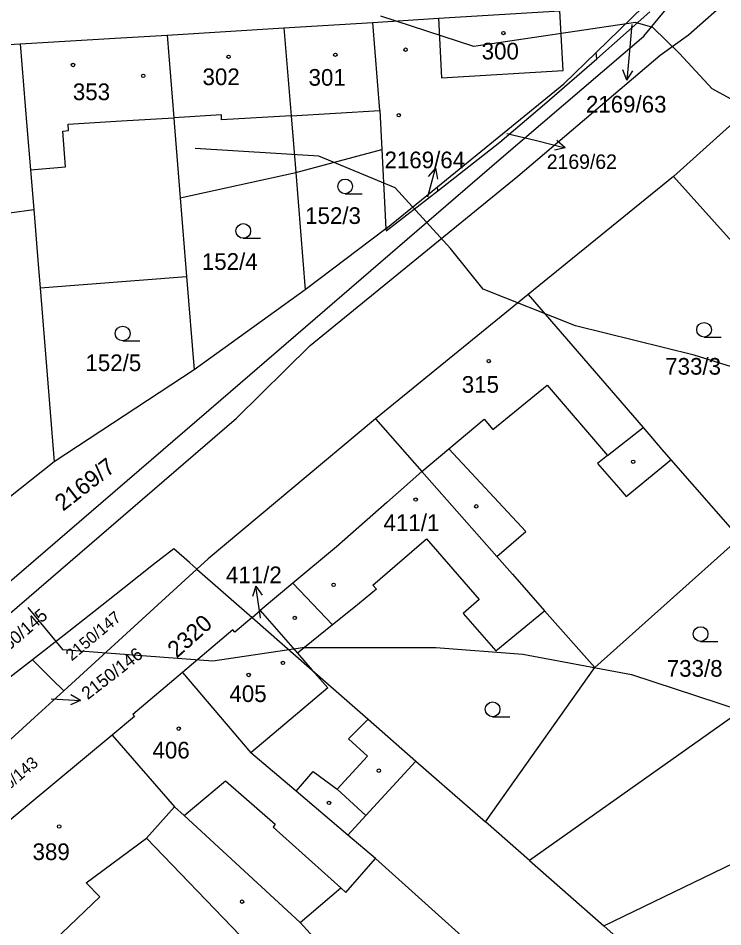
# Model space of a CAD drawing. Extents: x -555860 to -552701, y -1187050 to -1182291.
# Drawn here: x -554519.6 to -554447.8, y -1185322.9 to -1185230.2 of the extents above; entities that cross this region are included whole.
import ezdxf

# ---------------------------------------------------------------- set-up
doc = ezdxf.new("R2010")
doc.units = 0
for name, color, linetype in [('CYKLISTI_stav', 7, 'Continuous'), ('LEG_2b', 7, 'Continuous'), ('Level 16', 7, 'Continuous'), ('Level 25', 7, 'Continuous'), ('Level 41', 7, 'Continuous'), ('Level 42', 7, 'Continuous'), ('navrh_BV', 7, 'Continuous'), ('stav_BV', 7, 'Continuous')]:
    doc.layers.add(name, color=color, linetype=linetype)

msp = doc.modelspace()

# ---------------------------------------------------------------- linework, layer by layer
at = {"layer": 'CYKLISTI_stav'}
for p, q in [((-554476.77, -1185230.24), (-554476.47, -1185236.31)), ((-554464.04, -1185235.56), (-554464.41, -1185229.48)), ((-554476.47, -1185236.31), (-554464.04, -1185235.56)), ((-554491.78, -1185240.18), (-554482.74, -1185239.64)), ((-554509.07, -1185240.71), (-554503.75, -1185240.39)), ((-554498.9, -1185240.1), (-554503.75, -1185240.39)), ((-554498.87, -1185240.6), (-554498.9, -1185240.1)), ((-554491.78, -1185240.18), (-554498.87, -1185240.6)), ((-554514.53, -1185241.03), (-554509.07, -1185240.71)), ((-554514.48, -1185241.7), (-554514.53, -1185241.03)), ((-554515.06, -1185241.75), (-554514.48, -1185241.7)), ((-554514.78, -1185245.38), (-554515.06, -1185241.75)), ((-554518.36, -1185245.68), (-554514.78, -1185245.38)), ((-554520.5, -1185250.08), (-554518.03, -1185249.73)), ((-554471.21, -1185272.17), (-554465.7, -1185267.67)), ((-554465.7, -1185267.67), (-554459.52, -1185274.84)), ((-554475.7, -1185274.15), (-554472.11, -1185271.11)), ((-554472.11, -1185271.11), (-554471.21, -1185272.17)), ((-554459.52, -1185274.84), (-554455.91, -1185271.99)), ((-554478.45, -1185276.47), (-554475.7, -1185274.15)), ((-554467.86, -1185282.6), (-554475.7, -1185274.15)), ((-554459.52, -1185274.84), (-554460.54, -1185275.65)), ((-554460.54, -1185275.65), (-554458.42, -1185278.1)), ((-554457.63, -1185279.01), (-554453.07, -1185275.26)), ((-554478.45, -1185276.47), (-554482.02, -1185279.62)), ((-554458.42, -1185278.1), (-554457.63, -1185279.01)), ((-554482.02, -1185279.62), (-554483.46, -1185280.89)), ((-554483.46, -1185280.89), (-554487.15, -1185284.14)), ((-554470.83, -1185285.12), (-554467.86, -1185282.6)), ((-554483.45, -1185288.05), (-554477.98, -1185283.34)), ((-554477.98, -1185283.34), (-554472.61, -1185289.53)), ((-554487.15, -1185284.14), (-554491.6, -1185287.86)), ((-554491.6, -1185287.86), (-554494.93, -1185290.65)), ((-554491.6, -1185287.86), (-554487.57, -1185292.1)), ((-554483.07, -1185288.46), (-554485.41, -1185290.36)), ((-554483.45, -1185288.05), (-554483.07, -1185288.46)), ((-554472.61, -1185289.53), (-554474.25, -1185290.96)), ((-554485.41, -1185290.36), (-554487.57, -1185292.1)), ((-554474.25, -1185290.96), (-554470.93, -1185294.77)), ((-554470.93, -1185294.77), (-554465.94, -1185290.67)), ((-554487.57, -1185292.1), (-554491.14, -1185295)), ((-554489.63, -1185296.73), (-554488.06, -1185298.53)), ((-554488.06, -1185298.53), (-554490.68, -1185300.76)), ((-554490.68, -1185300.76), (-554495.88, -1185305.17)), ((-554485.94, -1185303.73), (-554483.92, -1185301.72)), ((-554484.01, -1185305.5), (-554485.94, -1185303.73)), ((-554487.1, -1185308.86), (-554484.01, -1185305.5)), ((-554491.27, -1185309.08), (-554489.55, -1185307.06)), ((-554489.55, -1185307.06), (-554487.1, -1185308.86)), ((-554502.7, -1185311.55), (-554498.49, -1185308)), ((-554498.49, -1185308), (-554493.4, -1185312.45)), ((-554487.1, -1185308.86), (-554484.17, -1185311.56)), ((-554506.53, -1185313.85), (-554503.67, -1185310.67)), ((-554493.4, -1185312.45), (-554493.62, -1185312.73)), ((-554493.62, -1185312.73), (-554486.73, -1185318.94)), ((-554512.67, -1185318.41), (-554506.53, -1185313.85)), ((-554506.53, -1185313.85), (-554497, -1185323.8)), ((-554511.3, -1185319.86), (-554512.67, -1185318.41)), ((-554519.81, -1185327.95), (-554511.3, -1185319.86))]:
    msp.add_line(p, q, dxfattribs=at)
at = {"layer": 'Level 16'}
for p, q in [((-554516.259, -1185299.65), (-554513.263, -1185299.813)), ((-554513.263, -1185299.813), (-554514.289, -1185300.258)), ((-554513.263, -1185299.813), (-554514.235, -1185299.259))]:
    msp.add_line(p, q, dxfattribs=at)
at = {"layer": 'Level 25'}
for p, q in [((-554486.282, -1185248.13), (-554484.532, -1185248.13)), ((-554496.672, -1185252.68), (-554494.922, -1185252.68)), ((-554449.692, -1185262.76), (-554447.942, -1185262.76)), ((-554508.962, -1185263.14), (-554507.212, -1185263.14)), ((-554450.042, -1185293.79), (-554448.292, -1185293.79)), ((-554471.252, -1185301.47), (-554469.502, -1185301.47))]:
    msp.add_line(p, q, dxfattribs=at)
for centre, radius in [((-554470.147, -1185231.749), 0.175), ((-554498.167, -1185234.159), 0.175), ((-554487.277, -1185233.959), 0.175), ((-554480.117, -1185233.439), 0.175), ((-554514.027, -1185234.999), 0.175), ((-554506.867, -1185236.109), 0.175), ((-554480.817, -1185240.129), 0.175), ((-554486.282, -1185247.38), 0.75), ((-554496.672, -1185251.93), 0.75), ((-554508.962, -1185262.39), 0.75), ((-554449.692, -1185262.01), 0.75), ((-554471.637, -1185265.199), 0.175), ((-554456.917, -1185275.469), 0.175), ((-554479.087, -1185279.329), 0.175), ((-554472.917, -1185280.019), 0.175), ((-554487.457, -1185288.019), 0.175), ((-554491.417, -1185291.399), 0.175), ((-554450.042, -1185293.04), 0.75), ((-554492.627, -1185295.989), 0.175), ((-554496.117, -1185297.219), 0.175), ((-554471.252, -1185300.72), 0.75), ((-554503.247, -1185302.689), 0.175), ((-554482.847, -1185306.979), 0.175), ((-554487.927, -1185310.269), 0.175), ((-554515.437, -1185312.669), 0.175), ((-554496.787, -1185320.339), 0.175)]:
    msp.add_circle(centre, radius, dxfattribs=at)
at = {"layer": 'Level 41'}
for points in [[(-554434.615, -1185245.176), (-554448.854, -1185237.442), (-554452.181, -1185233.842), (-554454.929, -1185231.169), (-554456.684, -1185230.681), (-554473.161, -1185233.113), (-554482.65, -1185230.017)], [(-554518.634, -1185290.338), (-554515.089, -1185294.626), (-554499.783, -1185295.786), (-554490.632, -1185294.399), (-554477.044, -1185294.398), (-554468.17, -1185295.092), (-554457.077, -1185297.172), (-554421.581, -1185308.819)]]:
    msp.add_lwpolyline(points, dxfattribs=at)
at = {"layer": 'Level 42'}
msp.add_lwpolyline([(-554307.578, -1185275.603), (-554312.621, -1185276.532), (-554318.143, -1185276.513), (-554330.037, -1185275.451), (-554360.572, -1185272.214), (-554370.555, -1185272.074), (-554381.648, -1185273.185), (-554387.194, -1185274.294), (-554397.431, -1185276.802), (-554403.067, -1185279.486), (-554450.699, -1185264.587), (-554462.81, -1185261.608), (-554472.204, -1185257.85), (-554475.53, -1185253.711), (-554481.166, -1185247.534), (-554488.95, -1185244.313), (-554501.564, -1185243.507)], dxfattribs=at)
at = {"layer": 'navrh_BV'}
for p, q in [((-554451.29, -1185231.91), (-554446.68, -1185227.84)), ((-554455.87, -1185229.05), (-554460.69, -1185233.73)), ((-554455.82, -1185232.07), (-554453.55, -1185229.31)), ((-554483.45, -1185230.66), (-554476.77, -1185230.24)), ((-554476.77, -1185230.24), (-554464.41, -1185229.48)), ((-554455.22, -1185229.58), (-554460.63, -1185234.37)), ((-554504.42, -1185231.95), (-554492.53, -1185231.22)), ((-554492.53, -1185231.22), (-554483.45, -1185230.66)), ((-554492.53, -1185231.22), (-554491.78, -1185240.18)), ((-554482.74, -1185239.64), (-554483.45, -1185230.66)), ((-554509.74, -1185232.28), (-554504.42, -1185231.95)), ((-554504.42, -1185231.95), (-554503.75, -1185240.39)), ((-554470.33, -1185244.46), (-554455.82, -1185232.07)), ((-554454.15, -1185233.99), (-554451.29, -1185231.91)), ((-554528.77, -1185233.45), (-554519.42, -1185232.84)), ((-554519.42, -1185232.84), (-554509.74, -1185232.28)), ((-554519.42, -1185232.84), (-554518.73, -1185241.28)), ((-554468.69, -1185246.34), (-554454.15, -1185233.99)), ((-554460.69, -1185233.73), (-554463.98, -1185236.92)), ((-554460.63, -1185234.37), (-554460.69, -1185233.73)), ((-554476.88, -1185247.43), (-554463.98, -1185236.92)), ((-554482.74, -1185239.64), (-554482.53, -1185243.63)), ((-554503.75, -1185240.39), (-554503.71, -1185240.89)), ((-554491.78, -1185240.18), (-554491.31, -1185245.96)), ((-554452.82, -1185246.39), (-554446.06, -1185240.32)), ((-554518.73, -1185241.28), (-554518.36, -1185245.68)), ((-554503.71, -1185240.89), (-554503.1, -1185248.55)), ((-554491.31, -1185245.96), (-554482.53, -1185243.63)), ((-554482.53, -1185243.63), (-554482.12, -1185251.7)), ((-554498.97, -1185269.16), (-554470.33, -1185244.46)), ((-554518.36, -1185245.68), (-554518.03, -1185249.73)), ((-554503.1, -1185248.55), (-554491.31, -1185245.96)), ((-554491.31, -1185245.96), (-554490.34, -1185257.92)), ((-554489.84, -1185263.62), (-554468.69, -1185246.34)), ((-554452.82, -1185246.39), (-554467.63, -1185258.4)), ((-554444.67, -1185255.45), (-554452.82, -1185246.39)), ((-554482.12, -1185251.7), (-554476.88, -1185247.43)), ((-554482.09, -1185251.92), (-554476.83, -1185247.85)), ((-554476.83, -1185247.85), (-554476.88, -1185247.43)), ((-554503.1, -1185248.55), (-554502.45, -1185256.56)), ((-554518.03, -1185249.73), (-554517.54, -1185255.76)), ((-554482.12, -1185251.7), (-554490.34, -1185257.92)), ((-554482.12, -1185251.7), (-554482.09, -1185251.92)), ((-554517.54, -1185255.76), (-554517.38, -1185257.74)), ((-554517.38, -1185257.74), (-554502.45, -1185256.56)), ((-554502.45, -1185256.56), (-554501.69, -1185266.08)), ((-554517.38, -1185257.74), (-554515.95, -1185275.49)), ((-554490.34, -1185257.92), (-554501.69, -1185266.08)), ((-554467.63, -1185258.4), (-554483.2, -1185271.09)), ((-554467.63, -1185258.4), (-554455.91, -1185271.99)), ((-554497.35, -1185271.02), (-554489.84, -1185263.62)), ((-554501.69, -1185266.08), (-554515.95, -1185275.49)), ((-554523.34, -1185290.16), (-554498.97, -1185269.16)), ((-554521.74, -1185291.99), (-554497.35, -1185271.02)), ((-554483.2, -1185271.09), (-554500.25, -1185285.36)), ((-554483.2, -1185271.09), (-554478.45, -1185276.47)), ((-554455.91, -1185271.99), (-554453.99, -1185274.21)), ((-554453.99, -1185274.21), (-554453.07, -1185275.26)), ((-554515.95, -1185275.49), (-554529.84, -1185286.45)), ((-554453.07, -1185275.26), (-554446.06, -1185283.25)), ((-554478.45, -1185276.47), (-554470.83, -1185285.12)), ((-554460.83, -1185296.47), (-554446.06, -1185283.25)), ((-554503.74, -1185284.35), (-554505.83, -1185285.95)), ((-554502.16, -1185285.73), (-554503.74, -1185284.35)), ((-554505.83, -1185285.95), (-554508.82, -1185288.34)), ((-554501.39, -1185286.41), (-554502.16, -1185285.73)), ((-554500.25, -1185285.36), (-554501.39, -1185286.41)), ((-554470.83, -1185285.12), (-554469.23, -1185286.94)), ((-554501.39, -1185286.41), (-554514.96, -1185298.82)), ((-554501.39, -1185286.41), (-554495.76, -1185291.35)), ((-554469.23, -1185286.94), (-554465.94, -1185290.67)), ((-554508.82, -1185288.34), (-554511.9, -1185290.78)), ((-554511.9, -1185290.78), (-554514.94, -1185293.15)), ((-554495.76, -1185291.35), (-554497.54, -1185292.84)), ((-554495.76, -1185291.35), (-554494.93, -1185290.65)), ((-554495.76, -1185291.35), (-554489.63, -1185296.73)), ((-554494.93, -1185290.65), (-554491.14, -1185295)), ((-554465.94, -1185290.67), (-554460.83, -1185296.47)), ((-554514.94, -1185293.15), (-554518.17, -1185295.68)), ((-554497.73, -1185292.61), (-554502.85, -1185296.95)), ((-554497.54, -1185292.84), (-554497.73, -1185292.61)), ((-554491.14, -1185295), (-554489.63, -1185296.73)), ((-554518.17, -1185295.68), (-554521.36, -1185298.16)), ((-554518.17, -1185295.68), (-554516.18, -1185297.63)), ((-554502.85, -1185296.95), (-554507.92, -1185301.25)), ((-554502.85, -1185296.95), (-554495.88, -1185305.17)), ((-554489.63, -1185296.73), (-554483.92, -1185301.72)), ((-554471.98, -1185312.21), (-554460.83, -1185296.47)), ((-554516.18, -1185297.63), (-554514.96, -1185298.82)), ((-554440.95, -1185297.34), (-554467.5, -1185316.15)), ((-554514.96, -1185298.82), (-554517.94, -1185301.54)), ((-554517.94, -1185301.54), (-554521.18, -1185304.51)), ((-554507.76, -1185301.44), (-554510.03, -1185303.36)), ((-554507.92, -1185301.25), (-554507.76, -1185301.44)), ((-554483.92, -1185301.72), (-554479.06, -1185306)), ((-554459.92, -1185322.81), (-554418.02, -1185302.53)), ((-554510.03, -1185303.36), (-554528.56, -1185318.75)), ((-554510.03, -1185303.36), (-554503.67, -1185310.67)), ((-554491.27, -1185309.08), (-554495.88, -1185305.17)), ((-554479.06, -1185306), (-554484.17, -1185311.56)), ((-554479.06, -1185306), (-554475.36, -1185309.25)), ((-554486.01, -1185313.55), (-554491.27, -1185309.08)), ((-554475.36, -1185309.25), (-554471.98, -1185312.21)), ((-554503.67, -1185310.67), (-554502.7, -1185311.55)), ((-554502.7, -1185311.55), (-554490.85, -1185322.45)), ((-554484.17, -1185311.56), (-554486.01, -1185313.55)), ((-554467.5, -1185316.15), (-554471.98, -1185312.21)), ((-554483.2, -1185315.93), (-554486.01, -1185313.55)), ((-554486.2, -1185319.41), (-554483.2, -1185315.93)), ((-554443.5, -1185351.5), (-554483.2, -1185315.93)), ((-554467.5, -1185316.15), (-554459.92, -1185322.81)), ((-554490.85, -1185322.45), (-554486.73, -1185318.94)), ((-554486.73, -1185318.94), (-554486.2, -1185319.41)), ((-554486.6, -1185327.18), (-554490.85, -1185322.45)), ((-554459.92, -1185322.81), (-554443.56, -1185337.18))]:
    msp.add_line(p, q, dxfattribs=at)
msp.add_lwpolyline([(-554476.83, -1185247.85), (-554470.51, -1185242.86), (-554465.96, -1185239), (-554460.63, -1185234.37)], dxfattribs=at)
at = {"layer": 'stav_BV'}
for p, q in [((-554457.04, -1185230.88), (-554457.29, -1185233.56)), ((-554457.29, -1185233.56), (-554457.552, -1185236.55)), ((-554457.552, -1185236.55), (-554457.963, -1185235.508)), ((-554457.552, -1185236.55), (-554456.965, -1185235.596)), ((-554469.79, -1185241.99), (-554466.76, -1185242.71)), ((-554466.76, -1185242.71), (-554463.848, -1185243.436)), ((-554463.848, -1185243.436), (-554464.699, -1185242.708)), ((-554463.848, -1185243.436), (-554464.941, -1185243.68)), ((-554477.85, -1185248.44), (-554477.073, -1185245.541)), ((-554477.073, -1185245.541), (-554477.816, -1185246.379)), ((-554477.073, -1185245.541), (-554476.849, -1185246.638)), ((-554495.378, -1185288.158), (-554495.734, -1185289.22)), ((-554494.96, -1185291.13), (-554495.378, -1185288.158)), ((-554495.378, -1185288.158), (-554494.742, -1185289.08)), ((-554494.92, -1185291.43), (-554494.96, -1185291.13))]:
    msp.add_line(p, q, dxfattribs=at)

# ---------------------------------------------------------------- texts
at = {"layer": 'LEG_2b'}
for s, height, p in [('300', 1.7, (-554472.36, -1185234.435)), ('302', 1.7, (-554500.82, -1185237.055)), ('301', 1.7, (-554490.01, -1185237.115)), ('353', 1.7, (-554514.04, -1185238.585)), ('2169/63', 1.7, (-554461.736, -1185239.855)), ('2169/64', 1.7, (-554482.266, -1185245.535)), ('2169/62', 1.479, (-554465.724, -1185245.599)), ('152/3', 1.7, (-554490.36, -1185251.215)), ('152/4', 1.7, (-554500.89, -1185255.895)), ('152/5', 1.7, (-554512.76, -1185266.225)), ('733/3', 1.7, (-554453.65, -1185266.585)), ('315', 1.7, (-554474.39, -1185268.435)), ('411/1', 1.7, (-554482.366, -1185282.535)), ('411/2', 1.7, (-554498.432, -1185287.855)), ('733/8', 1.7, (-554453.49, -1185297.395)), ('405', 1.7, (-554498.08, -1185299.975)), ('406', 1.7, (-554505.92, -1185305.735)), ('389', 1.7, (-554518.15, -1185316.095))]:
    msp.add_text(s, height=height, dxfattribs=at).set_placement(p)
for s, height, rotation, p in [('2169/7', 1.7, 38, (-554515.038, -1185280.574)), ('2150/147', 1.2, 40, (-554514.147, -1185295.839)), ('2320', 1.7, 42, (-554503.445, -1185295.565))]:
    msp.add_text(s, height=height, rotation=rotation, dxfattribs=at).set_placement(p)
at = {"layer": 'Level 16'}
for s, height, rotation, p in [('2150/145', 1.3, 40.5, (-554522.025, -1185296.041)), ('2150/146', 1.3, 37.8, (-554512.522, -1185299.794)), ('2150/143', 1.2, 40.5, (-554522.56, -1185310.706))]:
    msp.add_text(s, height=height, rotation=rotation, dxfattribs=at).set_placement(p)

doc.saveas('drawing.dxf')
